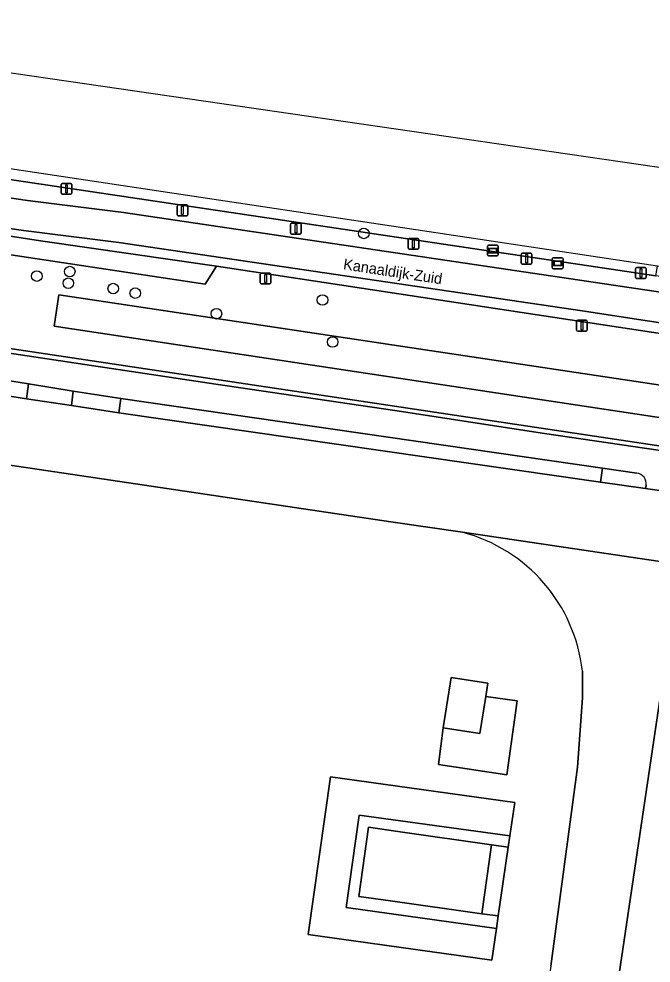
# Model space of a CAD drawing. Extents: x 163043 to 165076, y 382019 to 382874.
# Drawn here: x 164225.7 to 164284.1, y 382615.2 to 382702.5 of the extents above; entities that cross this region are included whole.
import ezdxf

# ---------------------------------------------------------------- set-up
doc = ezdxf.new("R2010")
doc.units = 0
for name, color, linetype in [('IMGEO_Afsluitpaal', 7, 'Continuous'), ('IMGEO_Boom', 7, 'Continuous'), ('IMGEO_Erf', 7, 'Continuous'), ('IMGEO_Fietspad_gesloten', 7, 'Continuous'), ('IMGEO_Fietspad_open', 7, 'Continuous'), ('IMGEO_Grasland_overig', 7, 'Continuous'), ('IMGEO_Groenvoorziening', 7, 'Continuous'), ('IMGEO_Hek', 7, 'Continuous'), ('IMGEO_Lichtmast', 7, 'Continuous'), ('IMGEO_Oever', 7, 'Continuous'), ('IMGEO_Openbare_ruimte_label', 7, 'Continuous'), ('IMGEO_Pand', 7, 'Continuous'), ('IMGEO_Rijbaan_lokaal_gesloten', 7, 'Continuous'), ('IMGEO_Rijbaan_lokaal_halfverhard', 7, 'Continuous'), ('IMGEO_Verklikker', 7, 'Continuous'), ('IMGEO_Voetpad_gesloten', 7, 'Continuous'), ('IMGEO_Voetpad_open', 7, 'Continuous'), ('IMGEO_Waterloop', 7, 'Continuous')]:
    doc.layers.add(name, color=color, linetype=linetype)

msp = doc.modelspace()

# ---------------------------------------------------------------- linework, layer by layer
at = {"layer": 'IMGEO_Afsluitpaal'}
for p, q in [((164229.602, 382686.35), (164229.602, 382687.15)), ((164229.602, 382687.15), (164229.602, 382686.35)), ((164229.702, 382687.25), (164230.492, 382687.25)), ((164230.492, 382687.25), (164229.702, 382687.25)), ((164230.592, 382687.15), (164230.592, 382686.35)), ((164230.592, 382686.35), (164230.592, 382687.15)), ((164230.492, 382686.25), (164229.702, 382686.25)), ((164229.702, 382686.25), (164230.492, 382686.25)), ((164240.409, 382685.256), (164241.199, 382685.256)), ((164241.199, 382685.256), (164240.409, 382685.256)), ((164240.309, 382684.356), (164240.309, 382685.156)), ((164240.309, 382685.156), (164240.309, 382684.356)), ((164241.299, 382685.156), (164241.299, 382684.356)), ((164241.299, 382684.356), (164241.299, 382685.156)), ((164241.199, 382684.256), (164240.409, 382684.256)), ((164240.409, 382684.256), (164241.199, 382684.256)), ((164250.795, 382682.658), (164250.795, 382683.458)), ((164250.795, 382683.458), (164250.795, 382682.658)), ((164250.895, 382683.558), (164251.685, 382683.558)), ((164251.685, 382683.558), (164250.895, 382683.558)), ((164251.785, 382683.458), (164251.785, 382682.658)), ((164251.785, 382682.658), (164251.785, 382683.458)), ((164251.685, 382682.558), (164250.895, 382682.558)), ((164250.895, 382682.558), (164251.685, 382682.558)), ((164261.649, 382681.255), (164261.649, 382682.055)), ((164261.649, 382682.055), (164261.649, 382681.255)), ((164261.749, 382682.155), (164262.539, 382682.155)), ((164262.539, 382682.155), (164261.749, 382682.155)), ((164262.639, 382682.055), (164262.639, 382681.255)), ((164262.639, 382681.255), (164262.639, 382682.055)), ((164262.539, 382681.155), (164261.749, 382681.155)), ((164261.749, 382681.155), (164262.539, 382681.155)), ((164272.098, 382679.889), (164272.098, 382680.689)), ((164272.098, 382680.689), (164272.098, 382679.889)), ((164272.198, 382680.789), (164272.988, 382680.789)), ((164272.988, 382680.789), (164272.198, 382680.789)), ((164273.088, 382680.689), (164273.088, 382679.889)), ((164273.088, 382679.889), (164273.088, 382680.689)), ((164272.988, 382679.789), (164272.198, 382679.789)), ((164272.198, 382679.789), (164272.988, 382679.789)), ((164282.657, 382678.56), (164282.657, 382679.36)), ((164282.657, 382679.36), (164282.657, 382678.56)), ((164282.757, 382679.46), (164283.547, 382679.46)), ((164283.547, 382679.46), (164282.757, 382679.46)), ((164283.647, 382679.36), (164283.647, 382678.56)), ((164283.647, 382678.56), (164283.647, 382679.36)), ((164283.547, 382678.46), (164282.757, 382678.46)), ((164282.757, 382678.46), (164283.547, 382678.46))]:
    msp.add_line(p, q, dxfattribs=at)
for points in [[(164230.022, 382687.125), (164230.172, 382687.125), (164230.172, 382686.375), (164230.022, 382686.375), (164230.022, 382687.125)], [(164240.729, 382685.131), (164240.879, 382685.131), (164240.879, 382684.381), (164240.729, 382684.381), (164240.729, 382685.131)], [(164251.215, 382683.433), (164251.365, 382683.433), (164251.365, 382682.683), (164251.215, 382682.683), (164251.215, 382683.433)], [(164262.069, 382682.03), (164262.219, 382682.03), (164262.219, 382681.28), (164262.069, 382681.28), (164262.069, 382682.03)], [(164272.518, 382680.664), (164272.668, 382680.664), (164272.668, 382679.914), (164272.518, 382679.914), (164272.518, 382680.664)], [(164283.077, 382679.335), (164283.227, 382679.335), (164283.227, 382678.585), (164283.077, 382678.585), (164283.077, 382679.335)]]:
    msp.add_lwpolyline(points, dxfattribs=at)
for centre, start, end in [((164229.702, 382687.15), 90, 180), ((164229.702, 382687.15), 90, 180), ((164230.492, 382687.15), 0, 90), ((164230.492, 382687.15), 360, 90), ((164229.702, 382686.35), 180, 270), ((164229.702, 382686.35), 180, 270), ((164230.492, 382686.35), 270, 0), ((164230.492, 382686.35), 270, 0), ((164240.409, 382685.156), 90, 180), ((164240.409, 382685.156), 90, 180), ((164241.199, 382685.156), 0, 90), ((164241.199, 382685.156), 360, 90), ((164240.409, 382684.356), 180, 270), ((164240.409, 382684.356), 180, 270), ((164241.199, 382684.356), 270, 0), ((164241.199, 382684.356), 270, 0), ((164250.895, 382683.458), 90, 180), ((164250.895, 382683.458), 90, 180), ((164251.685, 382683.458), 0, 90), ((164251.685, 382683.458), 360, 90), ((164250.895, 382682.658), 180, 270), ((164250.895, 382682.658), 180, 270), ((164251.685, 382682.658), 270, 0), ((164251.685, 382682.658), 270, 0), ((164261.749, 382682.055), 90, 180), ((164261.749, 382682.055), 90, 180), ((164262.539, 382682.055), 0, 90), ((164262.539, 382682.055), 360, 90), ((164261.749, 382681.255), 180, 270), ((164261.749, 382681.255), 180, 270), ((164262.539, 382681.255), 270, 0), ((164262.539, 382681.255), 270, 0), ((164272.198, 382680.689), 90, 180), ((164272.198, 382680.689), 90, 180), ((164272.988, 382680.689), 0, 90), ((164272.988, 382680.689), 360, 90), ((164272.198, 382679.889), 180, 270), ((164272.198, 382679.889), 180, 270), ((164272.988, 382679.889), 270, 0), ((164272.988, 382679.889), 270, 0), ((164282.757, 382679.36), 90, 180), ((164282.757, 382679.36), 90, 180), ((164283.547, 382679.36), 0, 90), ((164283.547, 382679.36), 360, 90), ((164282.757, 382678.56), 180, 270), ((164282.757, 382678.56), 180, 270), ((164283.547, 382678.56), 270, 0), ((164283.547, 382678.56), 270, 0)]:
    msp.add_arc(centre, 0.1, start, end, dxfattribs=at)
at = {"layer": 'IMGEO_Boom'}
for centre in [(164257.564, 382682.622), (164227.358, 382678.681), (164230.397, 382679.094), (164230.264, 382678.019), (164234.416, 382677.526), (164236.449, 382677.108), (164253.745, 382676.472), (164243.947, 382675.2), (164254.686, 382672.587)]:
    msp.add_circle(centre, 0.489, dxfattribs=at)
at = {"layer": 'IMGEO_Erf'}
for points in [[(164266.67, 382654.994), (164260.052, 382655.975), (164189.873, 382666.404), (164136.351, 382674.357)], [(164274.849, 382614.886), (164277.287, 382633.284), (164277.747, 382639.677), (164277.747, 382642.16)], [(164284.922, 382639.723), (164262.292, 382487.077), (164265.453, 382486.617), (164271.053, 382483.385), (164273.416, 382482.021), (164274.926, 382481.15), (164277.196, 382479.84), (164286.848, 382473.996), (164321.655, 382469.254), (164323.644, 382468.983), (164327.596, 382468.362), (164355.307, 382464.284)]]:
    msp.add_lwpolyline(points, dxfattribs=at)
for points in [[(164265.618, 382641.575), (164269.009, 382641.054), (164268.821, 382639.829), (164271.741, 382639.402), (164270.76, 382632.57), (164264.461, 382633.531), (164264.9, 382636.905)], [(164254.489, 382632.391), (164271.51, 382630.01), (164271.059, 382626.928), (164270.907, 382625.888), (164269.977, 382619.533), (164269.808, 382618.379), (164269.38, 382615.45), (164252.42, 382617.799)]]:
    msp.add_lwpolyline(points, close=True, dxfattribs=at)
msp.add_arc((164262.872, 382640.518), 14.966, 6.29771, 75.29711, dxfattribs=at)
at = {"layer": 'IMGEO_Fietspad_gesloten'}
for points in [[(164235.353, 382684.544), (164226.499, 382685.654), (164210.531, 382688.005), (164187.425, 382691.718), (164086.535, 382706.991), (164052.689, 382711.933), (164052.707, 382712.032), (163983.801, 382722.229), (163935.706, 382729.346), (163935.195, 382726.449), (163983.267, 382719.369), (164086.122, 382704.221), (164199.47, 382687.051), (164210.098, 382685.238), (164226.112, 382682.881), (164234.944, 382681.774), (164277.721, 382675.455), (164283.956, 382674.503), (164395.881, 382657.418)], [(164348.549, 382652.847), (164290.618, 382661.731), (164274.246, 382664.122), (164260.421, 382666.239), (164243.892, 382668.687), (164144.227, 382683.652), (164122.999, 382686.706), (164101.013, 382689.99), (164076.371, 382693.779), (164055.275, 382696.952), (164027.346, 382701.078)], [(164081.963, 382690.17), (164085.337, 382689.671), (164218.724, 382669.945), (164222.693, 382669.32), (164226.593, 382668.706), (164230.721, 382668.056), (164235.103, 382667.366), (164279.62, 382660.929), (164282.787, 382660.471)], [(164590.104, 382630.982), (164578.835, 382632.681), (164577.398, 382632.938), (164564.454, 382634.881), (164543.129, 382638.083), (164514.059, 382642.549), (164454.954, 382651.33), (164396.302, 382660.186), (164284.348, 382677.276), (164278.139, 382678.223), (164235.353, 382684.544)], [(164283.63, 382659.335), (164283.586, 382659.038), (164286.356, 382658.629), (164286.399, 382658.925)]]:
    msp.add_lwpolyline(points, dxfattribs=at)
msp.add_arc((164282.642, 382659.482), 0.999, 351.51941, 81.63714, dxfattribs=at)
at = {"layer": 'IMGEO_Fietspad_open'}
msp.add_lwpolyline([(164230.721, 382668.056), (164226.593, 382668.706), (164226.4, 382667.346), (164230.555, 382666.711)], close=True, dxfattribs=at)
at = {"layer": 'IMGEO_Grasland_overig'}
msp.add_lwpolyline([(164257.145, 382628.855), (164271.059, 382626.928), (164271.51, 382630.01), (164254.489, 382632.391), (164252.42, 382617.799), (164269.38, 382615.45), (164269.808, 382618.379), (164255.932, 382620.301)], close=True, dxfattribs=at)
at = {"layer": 'IMGEO_Groenvoorziening'}
for points in [[(163481.754, 382795.747), (163600.156, 382778.493), (163659.313, 382769.79), (163694.748, 382764.503), (163718.274, 382760.992), (163718.279, 382761.093), (163777.459, 382752.55), (163894.236, 382735.483), (163935.706, 382729.346), (163983.801, 382722.229), (164052.707, 382712.032), (164052.689, 382711.933), (164086.535, 382706.991), (164187.425, 382691.718), (164210.531, 382688.005), (164226.499, 382685.654), (164235.353, 382684.544), (164278.139, 382678.223), (164284.348, 382677.276), (164396.302, 382660.186)], [(164518.363, 382627.934), (164282.56, 382663.334), (164217.654, 382673.071), (164197.416, 382676.273), (164103.911, 382690.521), (164080.424, 382694.019), (163981.599, 382708.675), (163943.506, 382714.374), (163916.499, 382718.52), (163873.328, 382724.839), (163846.1, 382728.875), (163828.805, 382731.358), (163693.062, 382751.358), (163550.623, 382772.334), (163535.412, 382774.595), (163500, 382779.474)], [(163500, 382779.474), (163535.412, 382774.595), (163550.623, 382772.334), (163693.062, 382751.358), (163828.805, 382731.358), (163846.1, 382728.875), (163873.328, 382724.839), (163916.499, 382718.52), (163943.506, 382714.374), (163981.599, 382708.675), (164080.424, 382694.019), (164103.911, 382690.521), (164197.416, 382676.273), (164217.654, 382673.071), (164282.56, 382663.334), (164518.363, 382627.934)], [(163892.468, 382731.136), (163941.474, 382723.93), (163961.285, 382721.227), (163982.93, 382717.564), (163996.375, 382715.584), (164000, 382714.899), (164033.89, 382710.212), (164058.333, 382706.95), (164206.976, 382683.343), (164242.916, 382677.936), (164243.958, 382679.585), (164227.926, 382681.903), (164167.934, 382691.092), (164106.209, 382700.449), (164038.676, 382710.503), (163982.946, 382718.817), (163942.52, 382724.63), (163797.091, 382745.94)], [(164619.098, 382628.475), (164619.495, 382628.716), (164577.644, 382634.593), (164500, 382645.865), (164326.615, 382672.419), (164284.549, 382678.701), (164223.393, 382687.834), (164004.158, 382721.056), (164000, 382721.521), (163996.616, 382722.002), (163984.14, 382724.047), (163984.256, 382724.667), (163957.081, 382728.483), (163893.441, 382737.78)], [(164396.201, 382656.226), (164325.735, 382667.171), (164243.958, 382679.585), (164242.916, 382677.936), (164206.976, 382683.343), (164206.667, 382681.093), (164057.739, 382703.917), (164058.333, 382706.95), (164033.89, 382710.212), (164033.447, 382707.465), (164000, 382713.362), (163982.692, 382716.025), (163982.93, 382717.564), (163961.285, 382721.227)], [(163899.357, 382720.169), (163941.301, 382713.95), (163972.988, 382709.208), (164001.814, 382704.896), (164027.346, 382701.078), (164055.275, 382696.952), (164076.371, 382693.779), (164101.013, 382689.99), (164122.999, 382686.706), (164144.227, 382683.652), (164243.892, 382668.687), (164260.421, 382666.239), (164274.246, 382664.122), (164290.618, 382661.731), (164348.549, 382652.847)]]:
    msp.add_lwpolyline(points, dxfattribs=at)
for points in [[(164229.404, 382676.946), (164337.676, 382660.687), (164416.831, 382649.811), (164431.81, 382647.485), (164450.463, 382644.939), (164486.154, 382640.159), (164500, 382638.008), (164542.074, 382631.472), (164541.631, 382628.303), (164500, 382634.602), (164485.669, 382636.85), (164404.8, 382648.538), (164314.828, 382661.081), (164228.966, 382674.036)], [(164235.103, 382667.366), (164234.926, 382666.043), (164279.429, 382659.636), (164279.62, 382660.929)]]:
    msp.add_lwpolyline(points, close=True, dxfattribs=at)
at = {"layer": 'IMGEO_Hek'}
for points in [[(164282.56, 382663.334), (164217.654, 382673.071), (164197.416, 382676.273), (164103.911, 382690.521), (164080.424, 382694.019), (163981.599, 382708.675)], [(164518.363, 382627.934), (164282.56, 382663.334)]]:
    msp.add_lwpolyline(points, dxfattribs=at)
at = {"layer": 'IMGEO_Lichtmast'}
for p, q in [((164247.99, 382678.054), (164247.99, 382678.854)), ((164247.99, 382678.854), (164247.99, 382678.054)), ((164248.09, 382678.954), (164248.88, 382678.954)), ((164248.88, 382678.954), (164248.09, 382678.954)), ((164248.98, 382678.854), (164248.98, 382678.054)), ((164248.98, 382678.054), (164248.98, 382678.854)), ((164248.88, 382677.954), (164248.09, 382677.954)), ((164248.09, 382677.954), (164248.88, 382677.954)), ((164277.216, 382673.69), (164277.216, 382674.49)), ((164277.216, 382674.49), (164277.216, 382673.69)), ((164277.316, 382674.59), (164278.106, 382674.59)), ((164278.106, 382674.59), (164277.316, 382674.59)), ((164278.206, 382674.49), (164278.206, 382673.69)), ((164278.206, 382673.69), (164278.206, 382674.49)), ((164278.106, 382673.59), (164277.316, 382673.59)), ((164277.316, 382673.59), (164278.106, 382673.59))]:
    msp.add_line(p, q, dxfattribs=at)
for points in [[(164248.41, 382678.829), (164248.56, 382678.829), (164248.56, 382678.079), (164248.41, 382678.079), (164248.41, 382678.829)], [(164277.636, 382674.465), (164277.786, 382674.465), (164277.786, 382673.715), (164277.636, 382673.715), (164277.636, 382674.465)]]:
    msp.add_lwpolyline(points, dxfattribs=at)
for centre, start, end in [((164248.09, 382678.854), 90, 180), ((164248.09, 382678.854), 90, 180), ((164248.88, 382678.854), 0, 90), ((164248.88, 382678.854), 360, 90), ((164248.09, 382678.054), 180, 270), ((164248.09, 382678.054), 180, 270), ((164248.88, 382678.054), 270, 0), ((164248.88, 382678.054), 270, 0), ((164277.316, 382674.49), 90, 180), ((164277.316, 382674.49), 90, 180), ((164278.106, 382674.49), 0, 90), ((164278.106, 382674.49), 360, 90), ((164277.316, 382673.69), 180, 270), ((164277.316, 382673.69), 180, 270), ((164278.106, 382673.69), 270, 0), ((164278.106, 382673.69), 270, 0)]:
    msp.add_arc(centre, 0.1, start, end, dxfattribs=at)
at = {"layer": 'IMGEO_Oever'}
msp.add_lwpolyline([(164000, 382722.456), (163984.256, 382724.667), (163984.14, 382724.047), (163996.616, 382722.002), (164000, 382721.521), (164004.158, 382721.056), (164223.393, 382687.834), (164284.549, 382678.701), (164284.681, 382679.592)], close=True, dxfattribs=at)
at = {"layer": 'IMGEO_Pand'}
for points in [[(164268.821, 382639.829), (164269.009, 382641.054), (164265.618, 382641.575), (164264.9, 382636.905), (164268.291, 382636.384)], [(164269.365, 382626.103), (164260.925, 382627.307), (164258.006, 382627.724), (164257.094, 382621.336), (164260.013, 382620.919), (164268.454, 382619.727)]]:
    msp.add_lwpolyline(points, close=True, dxfattribs=at)
at = {"layer": 'IMGEO_Rijbaan_lokaal_gesloten'}
for points in [[(164451.732, 382634.171), (164290.568, 382658.006), (164286.356, 382658.629), (164283.586, 382659.038), (164279.429, 382659.636), (164234.926, 382666.043), (164230.555, 382666.711), (164226.4, 382667.346), (164222.501, 382667.942), (164218.524, 382668.55), (164085.142, 382688.386), (164080.784, 382689.031), (164078.014, 382689.44), (164073.871, 382690.053), (164017.784, 382698.347), (164013.588, 382698.968), (164010.818, 382699.378), (164006.839, 382699.966), (164000, 382700.978), (163854.781, 382722.338)], [(164136.351, 382674.357), (164189.873, 382666.404), (164260.052, 382655.975), (164266.67, 382654.994), (164293.437, 382651.026), (164300.725, 382649.946), (164344.658, 382643.506), (164443.557, 382629.092), (164467.198, 382625.55), (164471.103, 382624.799), (164473.37, 382624.1), (164473.449, 382624.088), (164473.779, 382624.039)], [(164293.437, 382651.026), (164266.67, 382654.994)], [(164277.747, 382642.16), (164277.747, 382639.677), (164277.287, 382633.284), (164274.849, 382614.886), (164255.42, 382488.077), (164255.806, 382488.021), (164262.292, 382487.077), (164284.922, 382639.723)]]:
    msp.add_lwpolyline(points, dxfattribs=at)
msp.add_arc((164262.872, 382640.518), 14.966, 6.29771, 75.29711, dxfattribs=at)
at = {"layer": 'IMGEO_Rijbaan_lokaal_halfverhard'}
for points in [[(163477.857, 382792.736), (163535.085, 382784.385), (163586.489, 382776.803), (163665.194, 382765.268), (163724.042, 382756.554), (163797.091, 382745.94), (163942.52, 382724.63), (163982.946, 382718.817), (164038.676, 382710.503), (164106.209, 382700.449), (164167.934, 382691.092), (164227.926, 382681.903), (164243.958, 382679.585), (164325.735, 382667.171), (164396.201, 382656.226)], [(164583.756, 382629.042), (164578.551, 382629.906), (164564.09, 382632.104), (164542.708, 382635.315), (164513.64, 382639.781), (164454.541, 382648.561), (164395.881, 382657.418), (164283.956, 382674.503), (164277.721, 382675.455), (164234.944, 382681.774), (164226.112, 382682.881), (164210.098, 382685.238), (164199.47, 382687.051), (164086.122, 382704.221), (163983.267, 382719.369), (163935.195, 382726.449), (163865.216, 382736.756), (163777.024, 382749.582)]]:
    msp.add_lwpolyline(points, dxfattribs=at)
at = {"layer": 'IMGEO_Verklikker'}
for p, q in [((164268.984, 382680.641), (164268.984, 382681.441)), ((164268.984, 382681.441), (164268.984, 382680.641)), ((164269.084, 382681.541), (164269.874, 382681.541)), ((164269.874, 382681.541), (164269.084, 382681.541)), ((164269.974, 382681.441), (164269.974, 382680.641)), ((164269.974, 382680.641), (164269.974, 382681.441)), ((164269.874, 382680.541), (164269.084, 382680.541)), ((164269.084, 382680.541), (164269.874, 382680.541)), ((164274.973, 382679.463), (164274.973, 382680.263)), ((164274.973, 382680.263), (164274.973, 382679.463)), ((164275.073, 382680.363), (164275.863, 382680.363)), ((164275.863, 382680.363), (164275.073, 382680.363)), ((164275.963, 382680.263), (164275.963, 382679.463)), ((164275.963, 382679.463), (164275.963, 382680.263)), ((164275.863, 382679.363), (164275.073, 382679.363)), ((164275.073, 382679.363), (164275.863, 382679.363))]:
    msp.add_line(p, q, dxfattribs=at)
for points in [[(164269.085, 382681.273), (164269.873, 382681.273), (164269.873, 382680.809), (164269.085, 382680.809), (164269.085, 382681.273)], [(164269.15, 382681.208), (164269.15, 382680.874), (164269.808, 382680.874), (164269.808, 382681.208), (164269.15, 382681.208)], [(164275.074, 382680.095), (164275.862, 382680.095), (164275.862, 382679.631), (164275.074, 382679.631), (164275.074, 382680.095)], [(164275.139, 382680.03), (164275.139, 382679.696), (164275.797, 382679.696), (164275.797, 382680.03), (164275.139, 382680.03)]]:
    msp.add_lwpolyline(points, dxfattribs=at)
for centre, start, end in [((164269.084, 382681.441), 90, 180), ((164269.084, 382681.441), 90, 180), ((164269.874, 382681.441), 0, 90), ((164269.874, 382681.441), 360, 90), ((164269.084, 382680.641), 180, 270), ((164269.084, 382680.641), 180, 270), ((164269.874, 382680.641), 270, 0), ((164269.874, 382680.641), 270, 0), ((164275.073, 382680.263), 90, 180), ((164275.073, 382680.263), 90, 180), ((164275.863, 382680.263), 0, 90), ((164275.863, 382680.263), 360, 90), ((164275.073, 382679.463), 180, 270), ((164275.073, 382679.463), 180, 270), ((164275.863, 382679.463), 270, 0), ((164275.863, 382679.463), 270, 0)]:
    msp.add_arc(centre, 0.1, start, end, dxfattribs=at)
at = {"layer": 'IMGEO_Voetpad_gesloten'}
msp.add_lwpolyline([(164264.461, 382633.531), (164270.76, 382632.57), (164271.741, 382639.402), (164268.821, 382639.829), (164268.291, 382636.384), (164264.9, 382636.905)], close=True, dxfattribs=at)
at = {"layer": 'IMGEO_Voetpad_open'}
for points in [[(164226.593, 382668.706), (164222.693, 382669.32), (164222.501, 382667.942), (164226.4, 382667.346)], [(164235.103, 382667.366), (164230.721, 382668.056), (164230.555, 382666.711), (164234.926, 382666.043)], [(164260.013, 382620.919), (164257.094, 382621.336), (164258.006, 382627.724), (164260.925, 382627.307), (164269.365, 382626.103), (164270.907, 382625.888), (164271.059, 382626.928), (164257.145, 382628.855), (164255.932, 382620.301), (164269.808, 382618.379), (164269.977, 382619.533), (164268.454, 382619.727)], [(164269.365, 382626.103), (164268.454, 382619.727), (164269.977, 382619.533), (164270.907, 382625.888)]]:
    msp.add_lwpolyline(points, close=True, dxfattribs=at)
msp.add_lwpolyline([(164282.787, 382660.471), (164279.62, 382660.929), (164279.429, 382659.636), (164283.586, 382659.038), (164283.63, 382659.335)], dxfattribs=at)
msp.add_arc((164282.642, 382659.482), 0.999, 351.51941, 81.63714, dxfattribs=at)
at = {"layer": 'IMGEO_Waterloop'}
for points in [[(163123.715, 382866.341), (163125.436, 382874.202), (163542.415, 382797.919), (163683.113, 382777.184), (164147.904, 382708.691), (165075.563, 382573.631)], [(164390.464, 382663.821), (164301.167, 382677.11), (164284.681, 382679.592), (164000, 382722.456), (163984.256, 382724.667), (163957.081, 382728.483), (163893.441, 382737.78), (163842.636, 382744.898), (163808.816, 382750), (163787.83, 382753.166), (163750, 382758.526), (163695.041, 382766.675), (163550.358, 382788.129), (163500, 382795.745)]]:
    msp.add_lwpolyline(points, dxfattribs=at)
msp.add_lwpolyline([(164542.074, 382631.472), (164500, 382638.008), (164486.154, 382640.159), (164450.463, 382644.939), (164431.81, 382647.485), (164416.831, 382649.811), (164337.676, 382660.687), (164229.404, 382676.946), (164228.966, 382674.036), (164314.828, 382661.081), (164404.8, 382648.538), (164485.669, 382636.85), (164500, 382634.602), (164541.631, 382628.303)], close=True, dxfattribs=at)

# ---------------------------------------------------------------- texts
at = {"layer": 'IMGEO_Openbare_ruimte_label'}
msp.add_text('Kanaaldijk-Zuid', height=1, rotation=351.25384, dxfattribs=at).set_placement((164255.611, 382679.315))

doc.saveas('drawing.dxf')
